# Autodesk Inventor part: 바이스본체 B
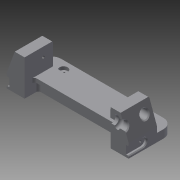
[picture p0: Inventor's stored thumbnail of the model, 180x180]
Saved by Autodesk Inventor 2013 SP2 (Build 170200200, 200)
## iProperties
Created: 2017-04
Part Number: 바이스본체 B
Material: 일반
Document SubType Name: Modeling
Designer: mduedu
Density: 1 g/cm^3
Author: mduedu
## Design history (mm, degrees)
sketch "스케치1"
  geometry: L1 (-75, 0)-(75, 0); L2 (-75, 0)-(-75, 17); L3 (-53, 17)-(53, 17); L4 (75, 17)-(75, 0); L5 (-75, 17)-(-65.173, 44); L6 (-65.173, 44)-(-53, 44); L7 (-53, 44)-(-53, 17); L8 (0, 0)-(0, 17); L9 (75, 17)-(65.173, 44); L10 (65.173, 44)-(53, 44); L11 (53, 44)-(53, 17); 1 further point
  constraints: 22 end point, 4 perpendicular, 2 horizontal alignment, 2 midpoint, 2 symmetric about line, 1 coincident, 1 collinear, 1 horizontal, 1 vertical
  dimensions: "d0" = 150 distance of L1.start L1.end; "d1" = 17 distance of L1.start L2.end; "d2" = 27 distance of L3.start L6.end; "d3" = 22 distance of L3.start L2.end; "d4" = 70 deg angle of L3 L5; "d54" = 20 deg angle of L9 L4
extrude "돌출1" new body sketch "스케치1" stored distance "d5" = 70; taper "d6" = 0 deg
sketch "스케치2"
  geometry: L1 (0, 70)-(106, 70) reference; L2 (106, 70)-(106, 0) reference; L3 (106, 0)-(0, 0) reference; L4 (0, 47)-(106, 47); L5 (106, 47)-(106, 23); L6 (106, 23)-(0, 23); L7 (0, 23)-(0, 47); L8 (0, 70)-(0, 0) reference; 2 further points
  constraints: 8 end point, 2 parallel, 2 point on line, 1 horizontal, 1 horizontal alignment, 1 midpoint, 1 perpendicular
  dimensions: "d7" = 24 distance between parallel lines of L6 L4
extrude "돌출2" cut sketch "스케치2" stored distance "d9" = 70; taper "d10" = 0 deg
sketch "스케치3"
  geometry: L1 (22, -23)-(128, -23) reference; L2 (128, -47)-(22, -47) reference; L3 (22, -18)-(128, -18); L4 (128, -52)-(22, -52); L5 (22, -18)-(22, -52); L6 (128, -18)-(128, -52); 1 further point
  constraints: 8 end point, 3 parallel, 2 point on line, 1 perpendicular
  dimensions: "d11" = 5 distance between parallel lines of L3 L1; "d12" = 5 distance between parallel lines of L4 L2
extrude "돌출3" cut sketch "스케치3" distance "d13" = 12; taper "d14" = 0 deg
fillet "모깎기1" dims "d15" = 3, "d16" = 3
sketch "스케치4"
  geometry: L1 (103, 23)-(3, 23) reference; L2 (0, 26)-(0, 0) reference; L3 (106, 0)-(0, 0) reference; L4 (106, 26)-(106, 0) reference; L5 (96, 0)-(90, 0); L6 (90, 0)-(90, 19.5); L7 (96, 19.5)-(96, 0); L8 (90, 19.5)-(96, 19.5); A1 r 3 centre (3, 26) between (0, 26) and (3, 23) reference; A2 r 3 centre (103, 26) between (103, 23) and (106, 26) reference; 1 further point
  constraints: 8 end point, 2 perpendicular, 1 horizontal, 1 parallel, 1 point on line
  dimensions: "d17" = 10 distance between parallel lines of L7 L4; "d18" = 6 distance between parallel lines of L7 L6; "d27" = 3.5 distance between parallel lines of L8 L1
extrude "돌출4" join sketch "스케치4" distance "d19" = 12; taper "d20" = 0 deg
chamfer "모따기1" distance "d21" = 3; stored, may be unused: second distance "d22" = 2, angle "d23" = 45 deg
chamfer "모따기2" distance "d24" = 3; stored, may be unused: second distance "d25" = 2, angle "d26" = 45 deg
sketch "스케치5"
  geometry: L1 (-15.5, 35.8)-(-15.5, -25.8) reference; L2 (19.5, 0)-(0, 0) reference; C1 r 6.5 at (9.5, 15); 1 further point
  constraints: 1 centre point
  dimensions: "d28" = 13 diameter of C1; "d30" = 15 distance from line of C1.centre L2; "d31" = 25 distance from line of C1.centre L1
extrude "돌출5" cut sketch "스케치5" stored distance "d32" = 12; taper "d33" = 0 deg
sketch "스케치6"
  geometry: C1 r 5 at (-10, 15); C2 r 5 at (-60, 15); A1 r 6.5 centre (-10, 15) between (-15.766, 12) and (-4.234, 12) reference; A2 r 6.5 centre (-60, 15) between (-65.766, 12) and (-54.234, 12) reference; 1 further point
  constraints: 2 centre point, 2 coincident
  dimensions: "d34" = 10 diameter of C1; "d35" = 10 diameter of C2 (= d34)
extrude "돌출6" cut sketch "스케치6" stored distance "d36" = 12; taper "d37" = 0 deg
chamfer "모따기3" distance "d38" = 1; stored, may be unused: second distance "d39" = 2, angle "d40" = 45 deg
chamfer "모따기4" distance "d41" = 1; stored, may be unused: second distance "d42" = 2, angle "d43" = 45 deg
sketch "스케치7"
  geometry: L1 (-35, 35.8)-(-35, -25.8) reference; L2 (-70, 0)-(0, 0) reference; C1 r 5 at (-35, 15); 1 further point
  constraints: 1 centre point, 1 point on line
  dimensions: "d44" = 10 diameter of C1; "d45" = 15 distance from line of C1.centre L2
extrude "돌출7" cut sketch "스케치7" stored distance "d46" = 12; taper "d47" = 0 deg
chamfer "모따기5" distance "d48" = 1; stored, may be unused: second distance "d49" = 2, angle "d50" = 45 deg
node "작업축1"
sketch "스케치8"
  geometry: L1 (-105, 32)-(105, 32) reference; L2 (58, 32)-(64, 32); L3 (64, 32)-(64, 40); L4 (64, 40)-(58, 40); L5 (58, 40)-(58, 32); L6 (53, 38)-(53, 26) reference; 1 further point
  constraints: 8 end point, 2 parallel, 1 horizontal, 1 perpendicular, 1 point on line
  dimensions: "d51" = 5 distance from line of L6 L2.start; "d52" = 6 distance of L3.end L4.end; "d53" = 16 diameter of L4 L1
revolve "회전1" sketch "스케치8" stored, may be unused: angle "d55" = 90 deg
fillet "모깎기2"
chamfer "모따기6" distance "d56" = 1; stored, may be unused: second distance "d57" = 2, angle "d58" = 45 deg
sketch "스케치9"
  geometry: L1 (17.5, 3)-(52.5, 3); L2 (52.5, 13)-(17.5, 13); L3 (70, 0)-(0, 0) reference; L4 (17.5, 8)-(52.5, 8); A1 r 5 centre (17.5, 8) between (17.5, 13) and (17.5, 3); A2 r 5 centre (52.5, 8) between (52.5, 3) and (52.5, 13); 3 further points
  constraints: 6 end point, 4 point on circle, 3 tangent, 2 centre point, 2 midpoint, 2 parallel, 1 horizontal, 1 vertical alignment
  dimensions: "d59" = 35 distance of L4.start L4.end; "d61" = 5 radius of A2; "d62" = 8 distance between parallel lines of L3 L4
extrude "돌출8" cut sketch "스케치9" distance "d63" = 3; taper "d64" = 0 deg
chamfer "모따기7" distance "d65" = 1; stored, may be unused: second distance "d66" = 2, angle "d67" = 45 deg
chamfer "모따기8" distance "d68" = 1; stored, may be unused: second distance "d69" = 2, angle "d70" = 45 deg
feature "분할1"
sketch "스케치10"
  geometry: A1 r 5 centre (0, 0) between (0, 5) and (0, -5) reference; 1 further point
  constraints: 1 coincident
hole "구멍1" sketch "스케치10" at (0, 0) diameter "d71" = 2.459; stored, may be unused: countersink angle "d75" = 90 deg, drill point angle "d77" = 120 deg; dims "d72" = 4.5, "d73" = 4, "d74" = 2, "d76" = 6
sketch "스케치11"
  geometry: L1 (0, 0)-(0, 27) reference; L2 (0, 27)-(-35, 27) reference; 2 further points
  dimensions: "d78" = 12 distance from line of point (-12, 15.5) L1; "d79" = 11.5 distance from line of point (-12, 15.5) L2
hole "구멍2" sketch "스케치11" at (-12, 15.5) diameter "d80" = 3.242; stored, may be unused: countersink angle "d84" = 90 deg, drill point angle "d86" = 120 deg; dims "d81" = 8, "d82" = 4, "d83" = 2, "d85" = 10
sketch "스케치12"
  geometry: L1 (-75, -35)-(-75, 0) reference; L2 (75, -35)-(75, 0) reference; L3 (75, -35)-(-75, -35); L4 (-75, -35)-(-75, -55); L5 (-75, -55)-(75, -55); L6 (75, -55)-(75, -35); 1 further point
  constraints: 8 end point, 2 parallel, 1 horizontal, 1 perpendicular, 1 point on line
  dimensions: "d87" = 20 distance of L3.end L4.end; "d89" = 150 distance of L4.end L5.end (derived)
extrude "돌출9" join sketch "스케치12" distance "d90" = 10; taper "d91" = 0 deg
sketch "스케치13"
  geometry: L1 (-75, 55)-(-75, 35) reference; L2 (75, 35)-(75, 55) reference; L3 (-75, 45)-(75, 45); 3 further points
  constraints: 2 end point, 2 midpoint, 2 point on line
  dimensions: "d92" = 50 horizontal distance of point (-50, 45) point (0, 0); "d93" = 100 distance of point (50, 45) point (-50, 45)
fillet "모깎기3" dims "d94" = 12
chamfer "모따기9" distance "d95" = 1; stored, may be unused: second distance "d96" = 2, angle "d97" = 45 deg
hole "구멍3" sketch "스케치13" diameter "d98" = 4.134; stored, may be unused: countersink angle "d102" = 90 deg, drill point angle "d104" = 118 deg; dims "d99" = 6, "d100" = 10, "d101" = 4, "d103" = 8
node "솔리드1"
mirror "대칭1"
mirror "대칭2"
mirror "대칭3"
mirror "대칭4"
node "투영된 루프1"
